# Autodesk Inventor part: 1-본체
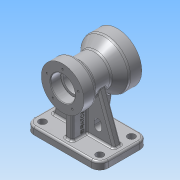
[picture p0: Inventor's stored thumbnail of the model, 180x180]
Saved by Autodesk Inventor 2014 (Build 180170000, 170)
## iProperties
Created: 2015-08
Part Number: 1-본체
Material: 알루미늄 6061
Document SubType Name: Modeling
Designer: study
Density: 2.71 g/cm^3
Appearance: 알루미늄 - 평지
Mass: 1062.79 g
Surface Area: 749.652 cm^2
Volume: 392.172 cm^3
Author: study
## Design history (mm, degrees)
sketch "스케치1"
  geometry: L1 (61, -40)-(-61, -40); L2 (-61, -40)-(-61, 40); L3 (-61, 40)-(61, 40); L4 (61, 40)-(61, -40); L5 (61, -40)-(-61, 40); L6 (-61, -40)-(61, 40); 1 further point
  constraints: 12 end point, 2 midpoint, 2 parallel, 1 horizontal, 1 perpendicular
  dimensions: "d0" = 122 distance of L2.end L3.end; "d1" = 80 distance of L3.end L1.start
extrude "돌출1" new body sketch "스케치1" distance "d2" = 12; taper "d3" = 0 deg
node "작업 평면1"
sketch "스케치2"
  geometry: L1 (-40, 90)-(50, 90); L2 (-40, 0)-(-40, 12) reference; L3 (-40, 12)-(40, 12) reference; L4 (40, 0)-(40, 12) reference; L5 (40, 0)-(-40, 0) reference; L6 (-40, 90)-(-40, 125); L7 (-40, 125)-(-20, 125); L8 (-20, 125)-(-14.804, 116); L9 (-14.804, 116)-(13.315, 116); L10 (13.315, 116)-(30, 130); L11 (30, 130)-(50, 130); L12 (50, 130)-(50, 90); 1 further point
  constraints: 16 end point, 3 perpendicular, 2 parallel, 1 horizontal, 1 vertical alignment
  dimensions: "d5" = 90 distance of L1.start L1.end; "d6" = 90 distance from line of L1.start L5; "d7" = 80 diameter of L11.end L1; "d8" = 70 diameter of L7 L1; "d9" = 20 distance of L6.end L7.end; "d10" = 20 distance of L10.end L11.end; "d11" = 40 deg angle of L1 L10; "d12" = 60 deg angle of L1 L8; "d13" = 52 diameter of L9 L1
revolve "회전1" sketch "스케치2" stored, may be unused: angle "d14" = 90 deg
node "작업 평면2"
sketch "스케치3"
  geometry: L1 (-40, 12)-(40, 12) reference; L2 (-40, 55)-(-20, 55) reference; L3 (30, 50)-(50, 50) reference; L4 (-30, 12)-(-30, 76.062); L5 (-30, 76.062)-(41.296, 76.062); L6 (41.296, 76.062)-(30, 12); L7 (-40, 55)-(-40, 125) reference; L8 (40, 0)-(40, 12) reference; 1 further point
  constraints: 6 end point, 2 point on line, 1 parallel, 1 perpendicular
  dimensions: "d16" = 10 distance between parallel lines of L4 L7; "d17" = 10 distance from line of L8 L6.end; "d18" = 80 deg angle of L6 L1; "d19" = 71.29581 distance of L4.end L5.end
extrude "돌출2" join sketch "스케치3" stored distance "d20" = 12; taper "d21" = 0 deg
node "작업 평면3"
sketch "스케치4"
  geometry: L1 (-61, 12)-(61, 12) reference; L2 (-51, 12)-(-23.65, 87.143); L3 (-23.65, 87.143)-(23.65, 87.143); L4 (23.65, 87.143)-(51, 12); L5 (61, 0)-(61, 12) reference; L6 (-61, 0)-(-61, 12) reference; C1 r 40 at (0, 90) reference; 1 further point
  constraints: 6 end point, 2 point on line, 1 equal length, 1 parallel
  dimensions: "d23" = 70 deg angle of L4 L1; "d24" = 10 distance from line of L5 L4.end; "d25" = 10 distance from line of L6 L2.start; "d26" = 47.30015 distance of L2.end L3.end
extrude "돌출3" join sketch "스케치4" stored distance "d27" = 12; taper "d28" = 0 deg
sketch "스케치5"
  geometry: L1 (-51, -12)-(-6, -12) reference; L2 (-18, -30)-(-18, -36); L3 (-30, -36)-(-30, -30); L4 (30, -30)-(30, -36); L5 (18, -36)-(18, -30); L6 (61, -12)-(-61, -12) reference; A1 r 6 centre (-24, -36) between (-30, -36) and (-18, -36); A2 r 6 centre (-24, -30) between (-18, -30) and (-30, -30); A3 r 6 centre (24, -36) between (18, -36) and (30, -36); A4 r 6 centre (24, -30) between (30, -30) and (18, -30); 2 further points
  constraints: 8 end point, 8 point on circle, 7 tangent, 4 centre point, 4 parallel, 2 equal radius, 1 coincident, 1 horizontal alignment, 1 perpendicular
  dimensions: "d29" = 12 distance between parallel lines of L5 L4; "d30" = 18 dimension on A3 A4; "d31" = 48 distance of A2.centre A4.centre; "d32" = 24 horizontal distance of point (0, 0) A4.centre; "d33" = 18 distance from line of L6 A4.centre
extrude "돌출4" cut sketch "스케치5" stored distance "d34" = 12; taper "d35" = 0 deg
sketch "스케치6"
  geometry: L1 (47, -26)-(-47, -26); L2 (-47, -26)-(-47, 26); L3 (-47, 26)-(47, 26); L4 (47, 26)-(47, -26); L5 (47, -26)-(-47, 26); L6 (-47, -26)-(47, 26); 5 further points
  constraints: 12 end point, 4 coincident, 2 midpoint, 2 parallel, 1 horizontal, 1 perpendicular
  dimensions: "d36" = 94 distance of L2.end L3.end; "d37" = 52 distance of L3.end L1.start
hole "구멍1" sketch "스케치6" at (-47, 26), (-47, -26), (47, -26), (47, 26) diameter "d38" = 12; stored, may be unused: countersink angle "d42" = 90 deg, drill point angle "d44" = 118 deg; dims "d39" = 6, "d40" = 4, "d41" = 2, "d43" = 8
hole "구멍2" diameter "d47" = 38; stored, may be unused: countersink angle "d51" = 90 deg, drill point angle "d53" = 0 deg; dims "d48" = 6, "d49" = 52, "d50" = 20, "d52" = 23, "d54" = 10, "d55" = 10
hole "구멍3" diameter "d58" = 32; stored, may be unused: countersink angle "d62" = 90 deg, drill point angle "d64" = 118 deg; dims "d56" = 10, "d57" = 10, "d59" = 6, "d60" = 40, "d61" = 17, "d63" = 23
sketch "스케치7"
  geometry: C1 r 26 at (0, 0) reference; 2 further points
  constraints: 1 vertical alignment
  dimensions: "d65" = 33 distance of C1.centre point (0, -33)
hole "구멍4" sketch "스케치7" at (0, -33) diameter "d66" = 3.242; stored, may be unused: countersink angle "d70" = 90 deg, drill point angle "d72" = 118 deg; dims "d67" = 10, "d68" = 40, "d69" = 17, "d71" = 13
sketch "스케치8"
  geometry: C1 r 20 at (0, 0) reference; 2 further points
  constraints: 1 vertical alignment
  dimensions: "d76" = 27 distance of C1.centre point (0, 27)
hole "구멍5" sketch "스케치8" at (0, 27) diameter "d77" = 3.242; stored, may be unused: countersink angle "d81" = 90 deg, drill point angle "d83" = 118 deg; dims "d78" = 10, "d79" = 40, "d80" = 17, "d82" = 13
fillet "모깎기1" dims "d87" = 5, "d88" = 0.3
chamfer "모따기1" distance "d89" = 1; stored, may be unused: second distance "d90" = 2, angle "d91" = 45 deg
fillet "모깎기2" dims "d92" = 3, "d94" = 14
fillet "모깎기3" dims "d93" = 3
sketch "스케치9"
  geometry: L1 (-12, 26)-(-12, -26) reference; L2 (-52.119, -30)-(-15, -30) reference; 2 further points
  constraints: 1 other
  dimensions: "d95" = 24 distance from line of point (-36, -14) L1; "d96" = 16 distance from line of point (-36, -14) L2
feature "엠보싱1" sketch "스케치9" dims "d0" = 122, "d1" = 80, "d12" = 60 deg, "d97" = 0.5, "d98" = 0
node "솔리드1"
pattern_circular "원형 패턴1" dims angle "d74" = 360 deg
pattern_circular "원형 패턴2" dims angle "d85" = 360 deg
other parameters: "d4" = 0, "d15" = 0, "d22" = 0
